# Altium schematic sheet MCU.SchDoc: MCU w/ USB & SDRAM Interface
size A2; DocumentNumber: 6; SheetNumber: 6; SheetTotal: 12
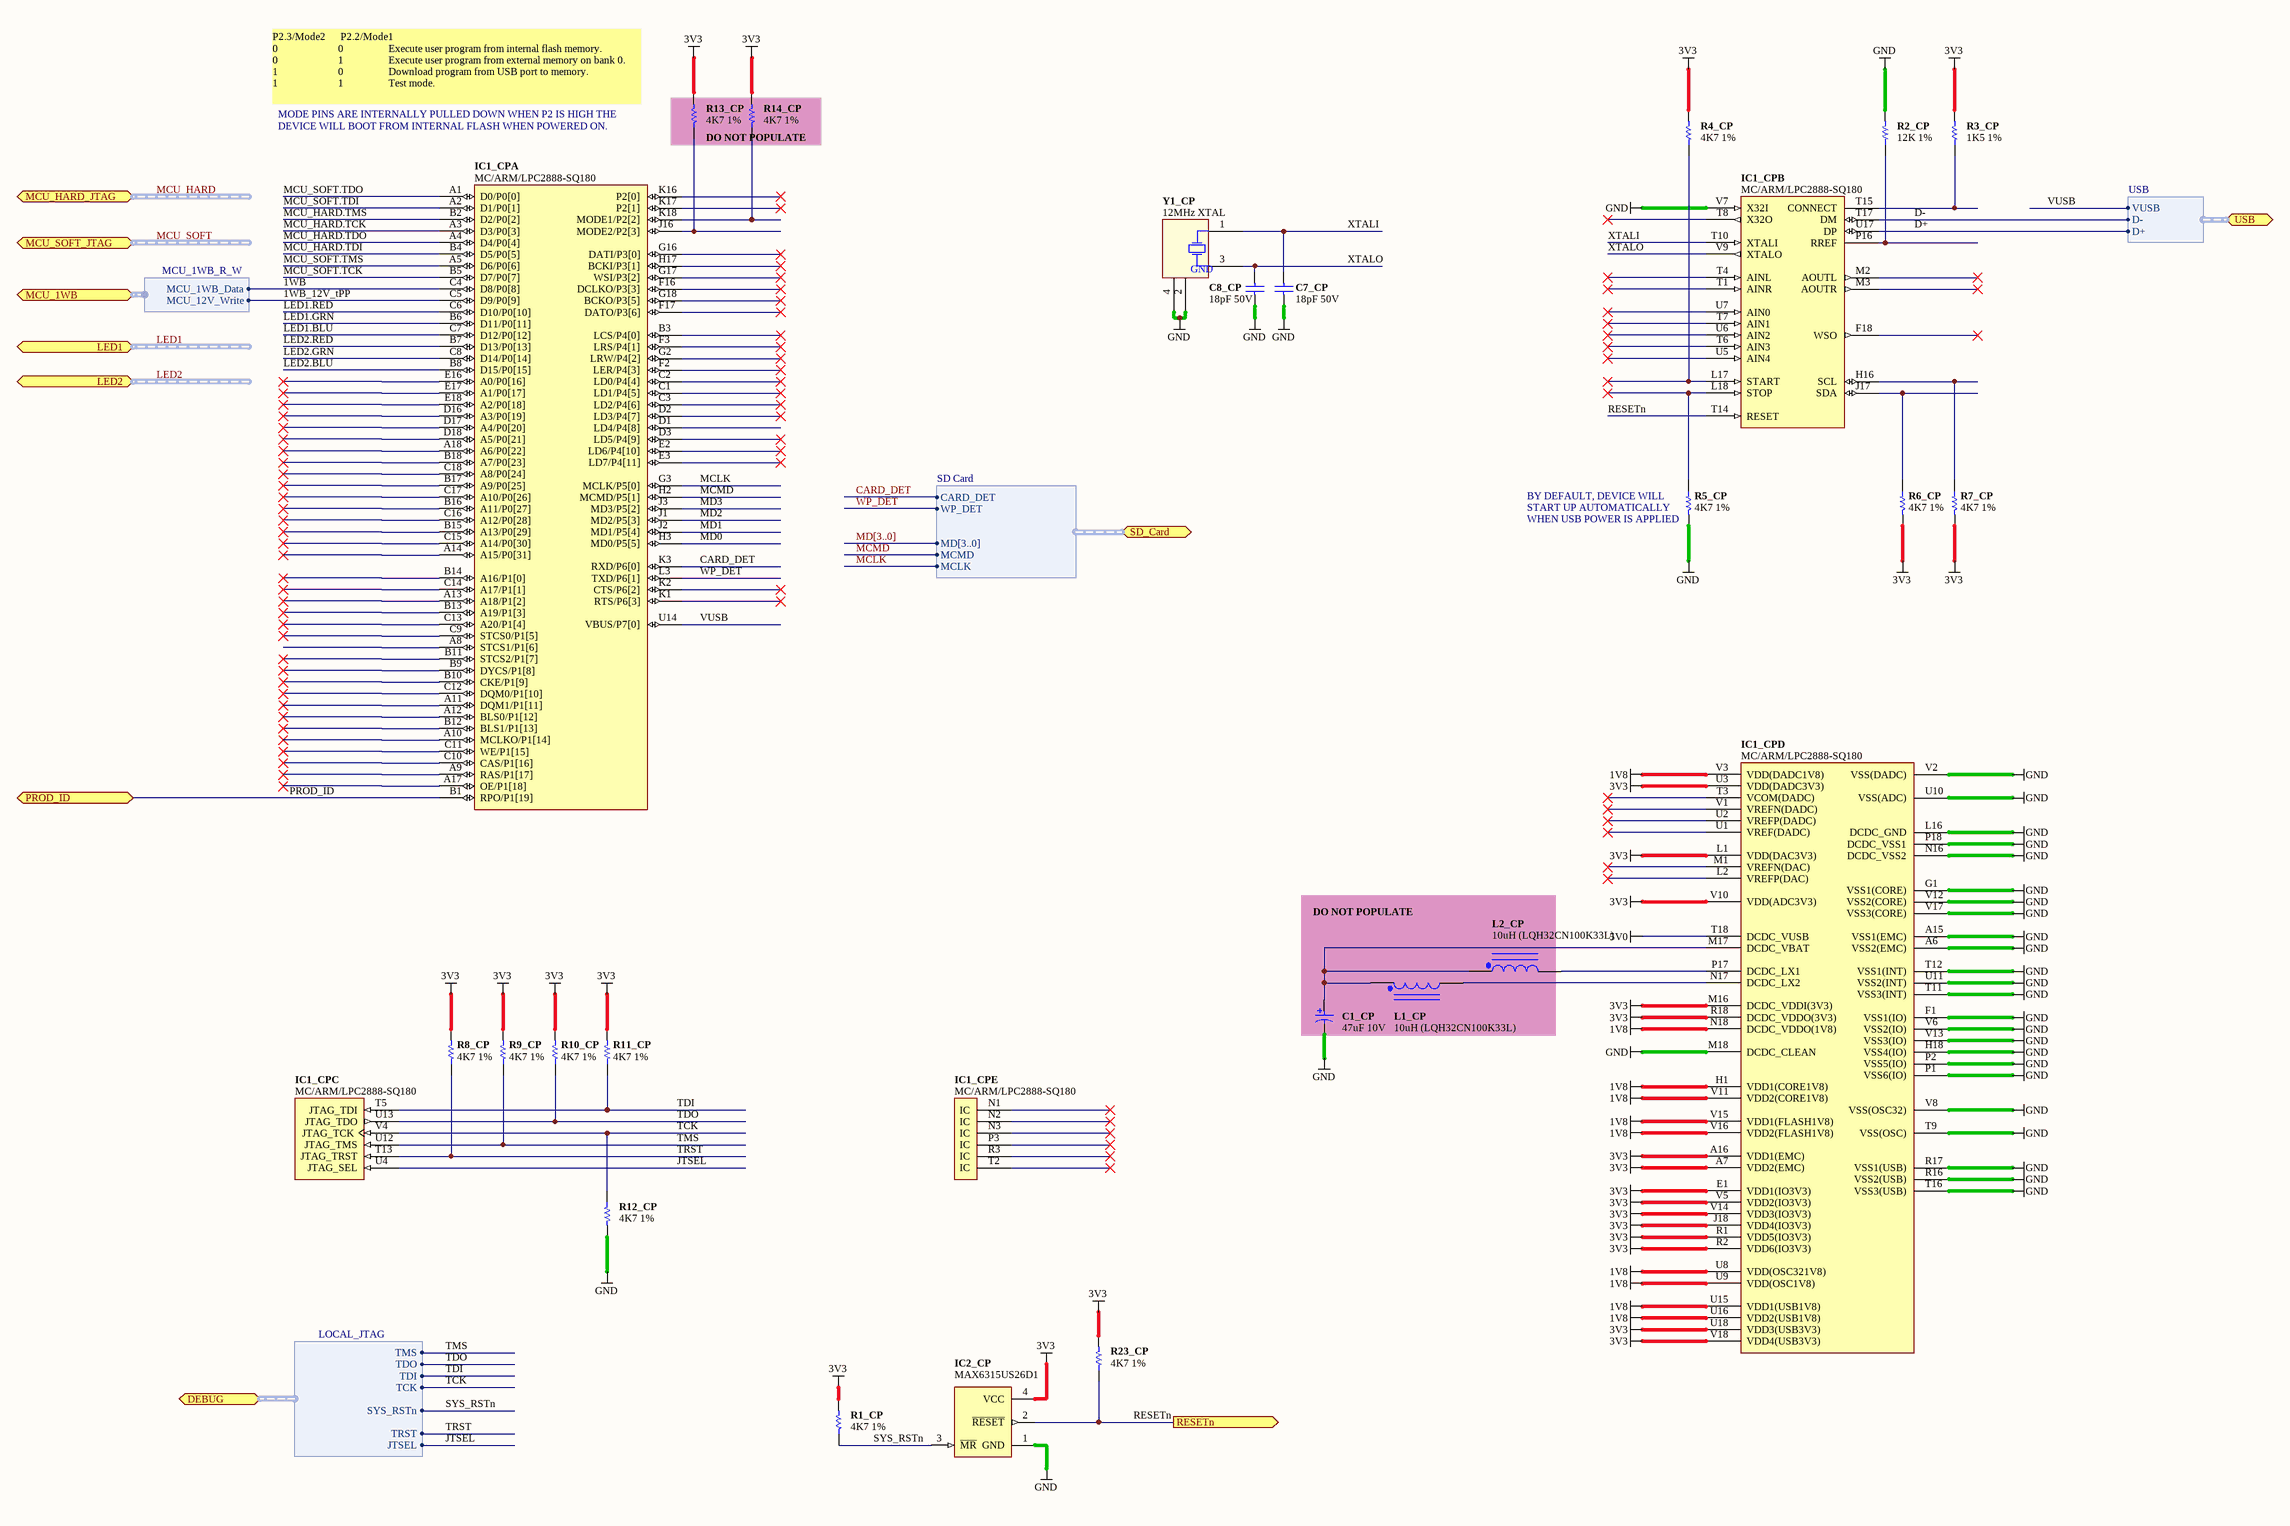
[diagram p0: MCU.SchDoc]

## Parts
C1_CP  47uF 10V  [CAPC3528-STAR]  (no BOM)
C7_CP  18pF 50V  [CAPC1005-STAR]
C8_CP  18pF 50V  [CAPC1005-STAR]
IC1_CP  MC/ARM/LPC2888-SQ180  [BGA50P18X18-180]  (parts A,B,C,D,E of 5)
IC2_CP  MAX6315US26D1  [SOT143]
L1_CP  10uH (LQH32CN100K33L)  [3261]  (no BOM)
L2_CP  10uH (LQH32CN100K33L)  [3261]  (no BOM)
R1_CP  4K7 1%  [RESC1005-STAR]
R2_CP  12K 1%  [RESC1005-STAR]
R3_CP  1K5 1%  [RESC1005-STAR]
R4_CP  4K7 1%  [RESC1005-STAR]
R5_CP  4K7 1%  [RESC1005-STAR]
R6_CP  4K7 1%  [RESC1005-STAR]
R7_CP  4K7 1%  [RESC1005-STAR]
R8_CP  4K7 1%  [RESC1005-STAR]
R9_CP  4K7 1%  [RESC1005-STAR]
R10_CP  4K7 1%  [RESC1005-STAR]
R11_CP  4K7 1%  [RESC1005-STAR]
R12_CP  4K7 1%  [RESC1005-STAR]
R13_CP  4K7 1%  [RESC1005-STAR]  (no BOM)
R14_CP  4K7 1%  [RESC1005-STAR]  (no BOM)
R23_CP  4K7 1%  [RESC1005-STAR]
Y1_CP  12MHz XTAL  [XTAL-200X126-4]

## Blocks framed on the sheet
DO NOT POPULATE: R13_CP R14_CP
DO NOT POPULATE: C1_CP L1_CP L2_CP

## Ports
DEBUG (harness LOCAL_JTAG), LED1 (harness RGB_LED), LED2 (harness RGB_LED), MCU_1WB (harness MCU_1WB_R_W), MCU_HARD_JTAG (harness JTAG), MCU_SOFT_JTAG (harness JTAG), PROD_ID (bidir), RESETn (out), SD_Card (harness SD Card), USB (harness USB)

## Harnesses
USB: VUSB, D-, D+
LOCAL_JTAG: TMS, TDO, TDI, TCK, SYS_RSTn, TRST, JTSEL
MCU_1WB_R_W: MCU_1WB_Data, MCU_12V_Write
SD Card: CARD_DET, WP_DET, MD[3..0], MCLK, MCMD

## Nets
1V8: IC1_CP.H1(VDD1(CORE1V8)) IC1_CP.N18(DCDC_VDDO(1V8)) IC1_CP.U8(VDD(OSC321V8)) IC1_CP.U9(VDD(OSC1V8)) IC1_CP.U15(VDD1(USB1V8)) IC1_CP.U16(VDD2(USB1V8)) IC1_CP.V3(VDD(DADC1V8)) IC1_CP.V11(VDD2(CORE1V8)) IC1_CP.V15(VDD1(FLASH1V8)) IC1_CP.V16(VDD2(FLASH1V8))
3V3: IC1_CP.A7(VDD2(EMC)) IC1_CP.A16(VDD1(EMC)) IC1_CP.E1(VDD1(IO3V3)) IC1_CP.J18(VDD4(IO3V3)) IC1_CP.L1(VDD(DAC3V3)) IC1_CP.M16(DCDC_VDDI(3V3)) IC1_CP.R1(VDD5(IO3V3)) IC1_CP.R2(VDD6(IO3V3)) IC1_CP.R18(DCDC_VDDO(3V3)) IC1_CP.U3(VDD(DADC3V3)) IC1_CP.U18(VDD3(USB3V3)) IC1_CP.V5(VDD2(IO3V3)) IC1_CP.V10(VDD(ADC3V3)) IC1_CP.V14(VDD3(IO3V3)) IC1_CP.V18(VDD4(USB3V3)) IC2_CP.4(VCC) R1_CP.2 R3_CP.2 R4_CP.2 R6_CP.2 R7_CP.2 R8_CP.2 R9_CP.2 R10_CP.2 R11_CP.2 R13_CP.2 R14_CP.2 R23_CP.2
5V0: IC1_CP.T18(DCDC_VUSB)
GND: C1_CP.2 C7_CP.2 C8_CP.2 IC1_CP.A6(VSS2(EMC)) IC1_CP.A15(VSS1(EMC)) IC1_CP.F1(VSS1(IO)) IC1_CP.G1(VSS1(CORE)) IC1_CP.H18(VSS4(IO)) IC1_CP.L16(DCDC_GND) IC1_CP.M18(DCDC_CLEAN) IC1_CP.N16(DCDC_VSS2) IC1_CP.P1(VSS6(IO)) IC1_CP.P2(VSS5(IO)) IC1_CP.P18(DCDC_VSS1) IC1_CP.R16(VSS2(USB)) IC1_CP.R17(VSS1(USB)) IC1_CP.T9(VSS(OSC)) IC1_CP.T11(VSS3(INT)) IC1_CP.T12(VSS1(INT)) IC1_CP.T16(VSS3(USB)) IC1_CP.U10(VSS(ADC)) IC1_CP.U11(VSS2(INT)) IC1_CP.V2(VSS(DADC)) IC1_CP.V6(VSS2(IO)) IC1_CP.V7(X32I) IC1_CP.V8(VSS(OSC32)) IC1_CP.V12(VSS2(CORE)) IC1_CP.V13(VSS3(IO)) IC1_CP.V17(VSS3(CORE)) IC2_CP.1(GND) R2_CP.2 R5_CP.2 R12_CP.2 Y1_CP.2(GND) Y1_CP.4(GND)
1WB: IC1_CP.C4(D8/P0[8]) ; port MCU_1WB.MCU_1WB_Data
1WB_12V_tPP: IC1_CP.C5(D9/P0[9]) ; port MCU_1WB.MCU_12V_Write
CARD_DET: IC1_CP.K3(RXD/P6[0]) ; port SD_Card.CARD_DET
D+: IC1_CP.U17(DP) ; port USB.D+
D-: IC1_CP.T17(DM) ; port USB.D-
JTSEL: IC1_CP.U4(JTAG_SEL) ; port DEBUG.JTSEL
LED1.BLU: IC1_CP.C7(D12/P0[12])
LED1.GRN: IC1_CP.B6(D11/P0[11])
LED1.RED: IC1_CP.C6(D10/P0[10])
LED2.BLU: IC1_CP.B8(D15/P0[15])
LED2.GRN: IC1_CP.C8(D14/P0[14])
LED2.RED: IC1_CP.B7(D13/P0[13])
MCLK: IC1_CP.G3(MCLK/P5[0]) ; port SD_Card.MCLK
MCMD: IC1_CP.H2(MCMD/P5[1]) ; port SD_Card.MCMD
MCU_HARD.TCK: IC1_CP.A3(D3/P0[3])
MCU_HARD.TDI: IC1_CP.B4(D5/P0[5])
MCU_HARD.TDO: IC1_CP.A4(D4/P0[4])
MCU_HARD.TMS: IC1_CP.B2(D2/P0[2])
MCU_SOFT.TCK: IC1_CP.B5(D7/P0[7])
MCU_SOFT.TDI: IC1_CP.A2(D1/P0[1])
MCU_SOFT.TDO: IC1_CP.A1(D0/P0[0])
MCU_SOFT.TMS: IC1_CP.A5(D6/P0[6])
MD0: IC1_CP.H3(MD0/P5[5])
MD1: IC1_CP.J2(MD1/P5[4])
MD2: IC1_CP.J1(MD2/P5[3])
MD3: IC1_CP.J3(MD3/P5[2])
PROD_ID: IC1_CP.B1(RPO/P1[19]) ; port PROD_ID
RESETn: IC1_CP.T14(RESET) IC2_CP.2(~{RESET}) R23_CP.1 ; port RESETn
SYS_RSTn: IC2_CP.3(~{MR}) R1_CP.1 ; port DEBUG.SYS_RSTn
TCK: IC1_CP.V4(JTAG_TCK) R12_CP.1 ; port DEBUG.TCK
TDI: IC1_CP.T5(JTAG_TDI) R11_CP.1 ; port DEBUG.TDI
TDO: IC1_CP.U13(JTAG_TDO) R10_CP.1 ; port DEBUG.TDO
TMS: IC1_CP.U12(JTAG_TMS) R9_CP.1 ; port DEBUG.TMS
TRST: IC1_CP.T13(JTAG_TRST) R8_CP.1 ; port DEBUG.TRST
VUSB: IC1_CP.U14(VBUS/P7[0]) ; port USB.VUSB
WP_DET: IC1_CP.L3(TXD/P6[1]) ; port SD_Card.WP_DET
XTALI: C7_CP.1 IC1_CP.T10(XTALI) Y1_CP.1(X1)
XTALO: C8_CP.1 IC1_CP.V9(XTALO) Y1_CP.3(X2)
NetC1_CP_1: C1_CP.1 IC1_CP.M17(DCDC_VBAT) L1_CP.1 L2_CP.1
NetIC1_CP_H16: IC1_CP.H16(SCL) R7_CP.1
NetIC1_CP_J16: IC1_CP.J16(MODE2/P2[3]) R13_CP.1
NetIC1_CP_J17: IC1_CP.J17(SDA) R6_CP.1
NetIC1_CP_K18: IC1_CP.K18(MODE1/P2[2]) R14_CP.1
NetIC1_CP_L17: IC1_CP.L17(START) R4_CP.1
NetIC1_CP_L18: IC1_CP.L18(STOP) R5_CP.1
NetIC1_CP_N17: IC1_CP.N17(DCDC_LX2) L1_CP.2
NetIC1_CP_P16: IC1_CP.P16(RREF) R2_CP.1
NetIC1_CP_P17: IC1_CP.P17(DCDC_LX1) L2_CP.2
NetIC1_CP_T15: IC1_CP.T15(CONNECT) R3_CP.1

Not connected (* = marked no-connect by the designer): IC1_CP A8(STCS1/P1[6]) A9(RAS/P1[17])* A10(MCLKO/P1[14])* A11(DQM1/P1[11])* A12(BLS0/P1[12])* A13(A18/P1[2])* A14(A15/P0[31])* A17(OE/P1[18])* A18(A6/P0[22])* B3(LCS/P4[0])* B9(DYCS/P1[8])* B10(CKE/P1[9])* B11(STCS2/P1[7])* B12(BLS1/P1[13])* B13(A19/P1[3])* B14(A16/P1[0])* B15(A13/P0[29])* B16(A11/P0[27])* B17(A9/P0[25])* B18(A7/P0[23])* C1(LD1/P4[5])* C2(LD0/P4[4])* C3(LD2/P4[6])* C9(STCS0/P1[5])* C10(CAS/P1[16])* C11(WE/P1[15])* C12(DQM0/P1[10])* C13(A20/P1[4])* C14(A17/P1[1])* C15(A14/P0[30])* C16(A12/P0[28])* C17(A10/P0[26])* C18(A8/P0[24])* D1(LD4/P4[8]) D2(LD3/P4[7])* D3(LD5/P4[9])* D16(A3/P0[19])* D17(A4/P0[20])* D18(A5/P0[21])* E2(LD6/P4[10])* E3(LD7/P4[11])* E16(A0/P0[16])* E17(A1/P0[17])* E18(A2/P0[18])* F2(LER/P4[3])* F3(LRS/P4[1])* F16(DCLKO/P3[3])* F17(DATO/P3[6])* F18(WSO)* G2(LRW/P4[2])* G16(DATI/P3[0])* G17(WSI/P3[2])* G18(BCKO/P3[5])* H17(BCKI/P3[1])* K1(RTS/P6[3])* K2(CTS/P6[2])* K16(P2[0])* K17(P2[1])* L2(VREFP(DAC))* M1(VREFN(DAC))* M2(AOUTL)* M3(AOUTR)* N1(IC)* N2(IC)* N3(IC)* P3(IC)* R3(IC)* T1(AINR)* T2(IC)* T3(VCOM(DADC))* T4(AINL)* T6(AIN3)* T7(AIN1)* T8(X32O)* U1(VREF(DADC))* U2(VREFP(DADC))* U5(AIN4)* U6(AIN2)* U7(AIN0)* V1(VREFN(DADC))*

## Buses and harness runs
bus MD[3..0]
harness LED1 = port LED1
harness LED2 = port LED2
harness MCU_HARD = port MCU_HARD_JTAG
harness MCU_SOFT = port MCU_SOFT_JTAG

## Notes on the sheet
- P2.3/Mode2      P2.2/Mode1
  0                        0                  Execute user program from internal flash memory.
  0                        1                  Execute user program from external memory on bank 0.
  1                        0                  Download program from USB port to memory.
  1                        1                  Test mode.
- MODE PINS ARE INTERNALLY PULLED DOWN WHEN P2 IS HIGH THE
- DEVICE WILL BOOT FROM INTERNAL FLASH WHEN POWERED ON.
- (near R5_CP) BY DEFAULT, DEVICE WILL
- START UP AUTOMATICALLY
- (near R5_CP) WHEN USB POWER IS APPLIED

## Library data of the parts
C1_CP = D-101-0001: Capacitor, Tantalum, 47uF 20% 10V MCCT-B (3528-12); Polarity: Polarized
C7_CP C8_CP = D-101-0089: Capacitor, Ceramic, 18pF 5% 50V 0402 (1005) COG; Polarity: Non-Polarized; Rated Voltage: 50 mV
IC1_CP = D-242-0001: 16/32-bit ARM microcontrollers; 8 kB cache, up to 1 MB flash,  High Speed USB 2.0 device, and SDRAM memory interface; Bit Width: Bits; Max Clock Frequency: Hz; Supply Voltage: mV
IC2_CP = D-243-0000: MAX6315, Open-Drain Output SOT Reset IC, Customized Reset Thresholds, Timeout Delays
L1_CP L2_CP = D-102-0011: Inductor, 10uH, 450mA, 0.3R, 1210 (3225) LQH32CN100K33L
R1_CP R4_CP R5_CP R6_CP R7_CP R8_CP R9_CP R10_CP R11_CP R12_CP R13_CP R14_CP R23_CP = D-100-0088: Resistor, 4K7 1% 0402 (1005); Power Rating: 63 mW; Resistance: 4.7 K
R2_CP = D-100-0002: Resistor, 12K 1% 0402; Power Rating: mW; Resistance: mR; Tolerance: %
R3_CP = D-100-0003: Resistor, 1K5 1% 0402; Power Rating: mW; Resistance: mR; Tolerance: %
Y1_CP = D-103-0029: Crystal, SMD, 12.000000MHz Stab=50ppm 10.0pF; Frequency Stability: 50 ppm; Load Capacitance: 10 pF; Nominal Operational Voltage: mV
